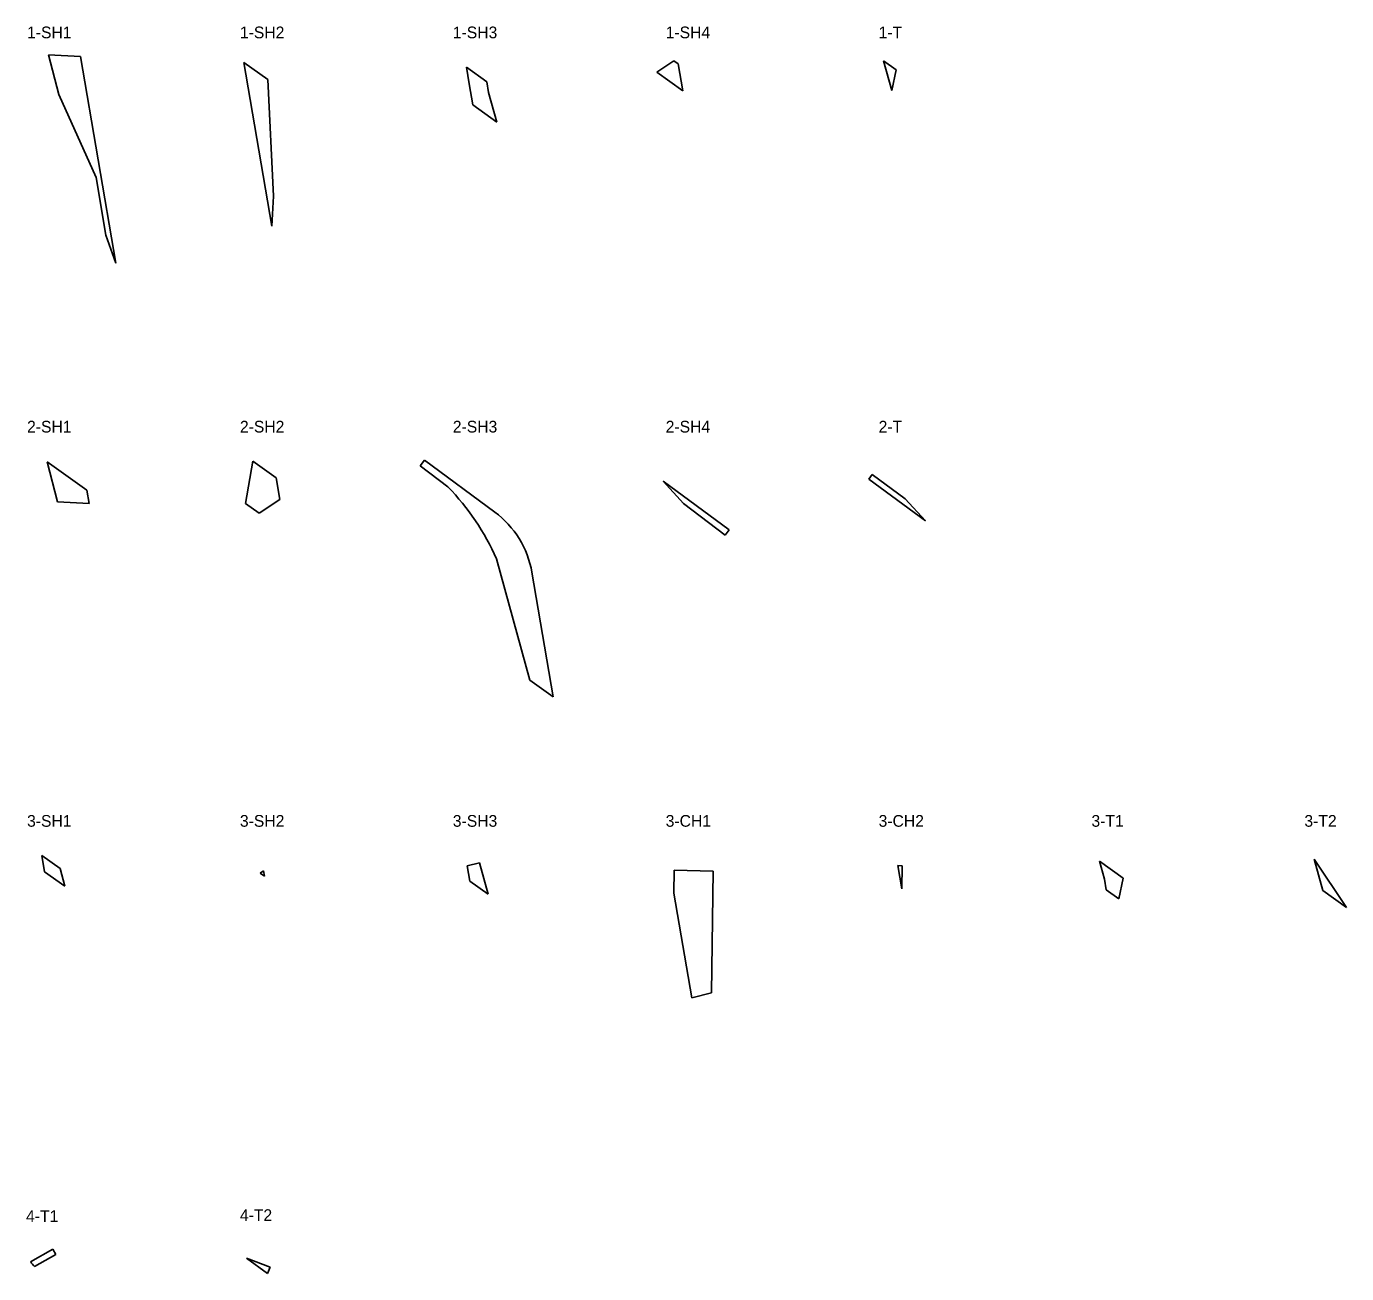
# Model space of a CAD drawing. Extents: x -262 to 1989, y -3630 to -1502.
import ezdxf

# ---------------------------------------------------------------- set-up
doc = ezdxf.new("R2010")
doc.units = 0
for name, color, linetype in [('RW_X_Esmt_RR', 7, 'Continuous'), ('SC_Scratch1', 7, 'Continuous'), ('SH_Text', 7, 'Continuous')]:
    doc.layers.add(name, color=color, linetype=linetype)

msp = doc.modelspace()

# ---------------------------------------------------------------- linework, layer by layer
at = {"layer": 'SC_Scratch1'}
for p, q in [((-170, -1553.9), (-170, -1553.9)), ((108.5, -1563.7), (108.5, -1563.7)), ((849.4, -1566.2), (849.4, -1566.2)), ((1199.4, -1561.3), (1199.4, -1561.3)), ((492.9, -1600.1), (492.9, -1600.1)), ((163.7, -2272.4), (163.8, -2272.4)), ((-155.1, -2316.4), (-155.1, -2316.4)), ((1236.6, -2308.1), (1236.6, -2308.1)), ((936.3, -2361), (936.3, -2361)), ((636.1, -2646), (636.1, -2646)), ((-231.3, -2944.4), (-231.3, -2944.4)), ((842.6, -2941.5), (842.6, -2941.5)), ((1223.8, -2933.9), (1223.8, -2933.9)), ((143.6, -2951.9), (143.6, -2951.9)), ((494, -2960.3), (494, -2960.3)), ((1576.2, -2957), (1576.2, -2957)), ((1948.7, -2976.5), (1948.7, -2976.5)), ((-248.6, -3617.9), (-248.6, -3617.9)), ((149.1, -3629.8), (149.1, -3629.8))]:
    msp.add_line(p, q, dxfattribs=at)
at = {"layer": 'SH_Text'}
for p, q in [((-207.1, -1618.3), (-224.3, -1551.1)), ((-224.3, -1551.1), (-170, -1553.9)), ((-170, -1553.9), (-109.8, -1906.4)), ((156.2, -1843.1), (108.5, -1563.7)), ((108.5, -1563.7), (149.3, -1592.8)), ((522.8, -1596.8), (488.1, -1572.1)), ((492.9, -1600.1), (488.1, -1572.1)), ((812.7, -1580.5), (842, -1560.9)), ((842, -1560.9), (849.4, -1566.2)), ((849.4, -1566.2), (857.2, -1612.3)), ((1199.4, -1561.3), (1213.5, -1611.9)), ((1199.4, -1561.3), (1221, -1576.7)), ((149.3, -1592.8), (159.1, -1791.9)), ((522.8, -1596.8), (525.9, -1614.9)), ((857.2, -1612.3), (812.7, -1580.5)), ((1221, -1576.7), (1213.5, -1611.9)), ((-143.5, -1760), (-207.1, -1618.3)), ((499.1, -1636.4), (492.9, -1600.1)), ((525.9, -1614.9), (539.9, -1665.5)), ((539.9, -1665.5), (499.1, -1636.4)), ((-126.6, -1858.6), (-143.5, -1760)), ((159.1, -1791.9), (156.2, -1843.1)), ((-109.8, -1906.4), (-126.6, -1858.6)), ((-209.4, -2313.6), (-226.9, -2245.3)), ((-226.9, -2245.3), (-158.9, -2293.7)), ((111.5, -2316.2), (123.8, -2243.9)), ((123.8, -2243.9), (163.7, -2272.4)), ((409.5, -2252), (416.5, -2242.5)), ((416.5, -2242.5), (536.5, -2330.9)), ((163.8, -2272.4), (170.1, -2309.4)), ((456.5, -2288), (409.5, -2252)), ((1174.3, -2274.6), (1180.3, -2266.6)), ((1180.3, -2266.6), (1236.6, -2308.1)), ((-158.9, -2293.7), (-155.1, -2316.4)), ((858.2, -2315.9), (823.9, -2278.2)), ((823.9, -2278.2), (936.3, -2361)), ((1271, -2345.8), (1174.3, -2274.6)), ((-155.1, -2316.4), (-209.4, -2313.6)), ((134.9, -2332.9), (111.5, -2316.2)), ((170.1, -2309.4), (134.9, -2332.9)), ((929.3, -2370.4), (858.2, -2315.9)), ((1271, -2345.8), (1236.6, -2308.1)), ((936.3, -2361), (929.3, -2370.4)), ((596.1, -2617.5), (539.5, -2410.6)), ((599.8, -2433.5), (636.1, -2646)), ((636.1, -2646), (596.1, -2617.5)), ((-231.3, -2944.4), (-236.1, -2916.4)), ((-236.1, -2916.4), (-204.9, -2938.6)), ((1608.4, -2955.4), (1567.9, -2926.5)), ((1567.9, -2926.5), (1576.2, -2957)), ((1934.1, -2922.9), (1948.7, -2976.5)), ((1934.1, -2922.9), (1989.2, -3005.4)), ((-196.6, -2969.1), (-231.3, -2944.4)), ((-204.9, -2938.6), (-196.6, -2969.1)), ((136.3, -2946.6), (142.1, -2942.8)), ((143.6, -2951.9), (136.3, -2946.6)), ((142.1, -2942.8), (143.6, -2951.9)), ((489.6, -2934.3), (510.5, -2928.9)), ((494, -2960.3), (489.6, -2934.3)), ((510.5, -2928.9), (525.1, -2982.5)), ((842.6, -2941.5), (842.1, -2980.7)), ((842.6, -2941.5), (909.2, -2943.2)), ((909.2, -2943.2), (906.2, -3150.9)), ((1223.8, -2933.9), (1231, -2934.1)), ((1230.5, -2973.3), (1223.8, -2933.9)), ((1231, -2934.1), (1230.5, -2973.3)), ((494, -2960.3), (525.1, -2982.5)), ((1576.2, -2957), (1579.3, -2975.1)), ((1608.4, -2955.4), (1600.9, -2990.5)), ((872.6, -3159.6), (842.1, -2980.7)), ((1579.3, -2975.1), (1600.9, -2990.5)), ((1989.2, -3005.4), (1948.7, -2976.5)), ((872.6, -3159.6), (906.2, -3150.9)), ((-255, -3610), (-217, -3588.3)), ((-212, -3597), (-248.6, -3617.9)), ((-217, -3588.3), (-212, -3597)), ((149.1, -3629.8), (113.4, -3603.5)), ((113.4, -3603.5), (153.4, -3618.7)), ((153.4, -3618.7), (149.1, -3629.8))]:
    msp.add_line(p, q, dxfattribs=at)
for centre, radius, start, end in [((152.8, -2582.9), 423.4, 24.0079, 44.1515), ((441.1, -2460.6), 161, 9.6848, 53.6336), ((-424.1, -3752.2), 221, 37.4284, 40.0549)]:
    msp.add_arc(centre, radius, start, end, dxfattribs=at)

# ---------------------------------------------------------------- texts
at = {"layer": 'RW_X_Esmt_RR'}
for s, p in [('1-SH1', (-261.1, -1522.6)), ('1-SH2', (101.9, -1522.6)), ('1-SH3', (465, -1522.6)), ('1-SH4', (828, -1522.6)), ('1-T', (1191.1, -1522.6)), ('2-SH1', (-261.1, -2195.1)), ('2-SH2', (101.9, -2195.1)), ('2-SH3', (465, -2195.1)), ('2-SH4', (828, -2195.1)), ('2-T', (1191.1, -2195.1)), ('3-SH1', (-261.1, -2867.6)), ('3-SH2', (101.9, -2867.6)), ('3-SH3', (465, -2867.6)), ('3-CH1', (828, -2867.6)), ('3-CH2', (1191.1, -2867.6)), ('3-T1', (1554.1, -2867.6)), ('3-T2', (1917.2, -2867.6)), ('4-T1', (-262.8, -3541.8)), ('4-T2', (101.9, -3540.1))]:
    msp.add_text(s, height=20, dxfattribs=at).set_placement(p)

doc.saveas('drawing.dxf')
